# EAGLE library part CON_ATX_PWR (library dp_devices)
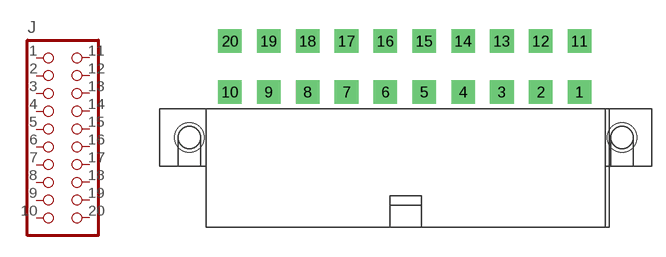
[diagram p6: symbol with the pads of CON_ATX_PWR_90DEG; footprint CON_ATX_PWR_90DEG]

Designator prefix J

## CON_ATX_PWR-90DEG  [CON_ATX_PWR_90DEG]
1  1  pas
2  3  pas
3  5  pas
4  7  pas
5  9  pas
6  11  pas
7  13  pas
8  15  pas
9  17  pas
10  19  pas
11  2  pas
12  4  pas
13  6  pas
14  8  pas
15  10  pas
16  12  pas
17  14  pas
18  16  pas
19  18  pas
20  20  pas

## Footprint CON_ATX_PWR_90DEG (pad centres in mm)
place with 9.7mm spacing from the edge of the board
drill 1.7 square: 1 18.8,4.93; 2 14.6,4.93; 3 10.4,4.93; 4 6.2,4.93; 5 2,4.93; 6 -2.2,4.93; 7 -6.4,4.93; 8 -10.6,4.93; 9 -14.8,4.93; 10 -19,4.93; 11 18.8,10.43; 12 14.6,10.43; 13 10.4,10.43; 14 6.2,10.43; 15 2,10.43; 16 -2.2,10.43; 17 -6.4,10.43; 18 -10.6,10.43; 19 -14.8,10.43; 20 -19,10.43
hole 3.2 at 23.4,0
hole 3.2 at -23.4,0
